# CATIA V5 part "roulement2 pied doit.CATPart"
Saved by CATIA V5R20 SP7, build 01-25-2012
Part number: roulement 2 pied doit
Bounding box of the stored display mesh (mm): x 10.048 to 24.056, y -79 to -65, z -18.487 to -7.224
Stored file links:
  F:\Travaux\Modélisations\CFAO_2011\CFAO_2011_MMS\CFAO_2011_MMS_DONE\CFAO_2011_MMS_jboiteux\Catia\roulement2 pied doit.CATPart
  U:\finthinkmotion\stepper.CATProduct
  F:\Travaux\Modélisations\CFAO_2011\CFAO_2011_MMS\CFAO_2011_MMS_DONE\CFAO_2011_MMS_jboiteux\Catia\support droit.CATPart
  F:\Travaux\Modélisations\CFAO_2011\CFAO_2011_MMS\CFAO_2011_MMS_DONE\CFAO_2011_MMS_jboiteux\Catia\Part1.CATPart
  F:\Travaux\Modélisations\CFAO_2011\CFAO_2011_MMS\CFAO_2011_MMS_DONE\CFAO_2011_MMS_jboiteux\Catia\entretoise pied droit.CATPart
  F:\Travaux\Modélisations\CFAO_2011\CFAO_2011_MMS\CFAO_2011_MMS_DONE\CFAO_2011_MMS_jboiteux\Catia\bati.CATPart
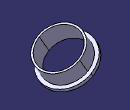
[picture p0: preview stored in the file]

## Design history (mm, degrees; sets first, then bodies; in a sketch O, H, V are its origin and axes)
Parameters
  `rayon tube` = 9 mm {= External.royontubebati}
External parameters (linked from other documents)
  External.royontubebati = 9 mm
Set1
  DatumSurface1: linked copy from another document
  DatumCurve1: linked copy from another document
  Point1: linked copy from another document
Body1 (main body)
  Sketch1 on face of DatumSurface1, origin (-1.9622, 0, -3.3987), H (0, 1, 0), V (-0.866, 0, 0.5)
    projected circle E1 centre (-72, -21.4454) radius 7 from edge of DatumCurve1
    circle A1 centre (-72, -21.4454) radius 5.5
    point P1 (-72, -21.4454)
    reference projected point E2 (-72, -21.4454) from Point1
    radius A1 = 5.5 {= `rayon tube` *5/9+0.5mm}
    coincidence: E2 P1
  Pad1: profile Sketch1, direction (-0.5, 0, -0.866), length 1
  Sketch2 on start face of Pad1, origin (-1.9622, 0, -3.3987), H (0, 1, 0), V (-0.866, 0, 0.5)
    projected circle E1 centre (-72, -21.4454) radius 5.5 from edge [start face of Pad1 | face of Pad1 from Sketch1.A1]
    circle A1 centre (-72, -21.4454) radius 6
    point P1 (-72, -21.4454)
    reference projected point E2 (-72, -21.4454) from Point1
    radius A1 = 6 {= `rayon tube` *5/9+1mm}
    coincidence: E2 P1
  Pad2: profile Sketch2, direction (0.5, 0, 0.866), length 4.5 {= `rayon tube` /2}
